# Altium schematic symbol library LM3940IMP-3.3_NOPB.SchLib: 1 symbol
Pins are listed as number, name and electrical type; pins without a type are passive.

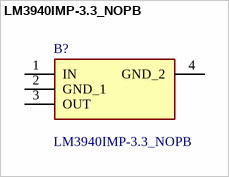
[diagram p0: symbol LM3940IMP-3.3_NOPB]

## LM3940IMP-3.3_NOPB
designator B?
LM3940IMP-3.3/NOPB, Low Dropout Voltage Regulator, 1A, 3.3 V, 4.5  7.5 Vin, 4-Pin SOT-223; Manufacturer_Name: Texas Instruments; Geometry.Height: 1.8mm
footprint SOT230P700X180-4N
pins: 1 IN, 2 GND_1, 3 OUT, 4 GND_2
